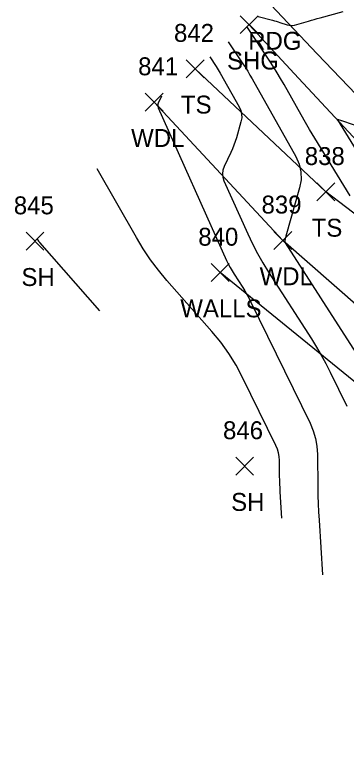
# Model space of a CAD drawing. Extents: x 1592612 to 1596497, y 111838 to 113741.
# Drawn here: x 1592636.6 to 1592673.5, y 113548.4 to 113631.2 of the extents above; entities that cross this region are included whole.
import ezdxf

# ---------------------------------------------------------------- set-up
doc = ezdxf.new("R2010")
doc.units = 0
for name, color, linetype in [('L_A', 7, 'Continuous'), ('L_I', 7, 'Continuous'), ('L_TIC', 7, 'Continuous'), ('LAWA', 7, 'Continuous'), ('LELB', 7, 'Continuous'), ('LSOGCMA', 7, 'Continuous'), ('LSOGCMI', 7, 'Continuous'), ('LWS', 7, 'Continuous'), ('P_A', 7, 'Continuous'), ('P_TIC', 7, 'Continuous'), ('PEU', 7, 'Continuous'), ('PSU', 7, 'Continuous')]:
    doc.layers.add(name, color=color, linetype=linetype)

msp = doc.modelspace()

# ---------------------------------------------------------------- linework, layer by layer
at = {"layer": 'L_TIC'}
for points in [[(1592655.68, 113624.229), (1592657.68, 113626.229)], [(1592657.68, 113624.229), (1592655.68, 113626.229)], [(1592651.114, 113620.499), (1592653.114, 113622.499)], [(1592653.114, 113620.499), (1592651.114, 113622.499)], [(1592670.27, 113610.482), (1592672.27, 113612.482)], [(1592672.27, 113610.482), (1592670.27, 113612.482)], [(1592637.809, 113604.981), (1592639.809, 113606.981)], [(1592639.809, 113604.981), (1592637.809, 113606.981)], [(1592665.454, 113605.066), (1592667.454, 113607.066)], [(1592667.454, 113605.066), (1592665.454, 113607.066)], [(1592658.477, 113601.479), (1592660.477, 113603.479)], [(1592660.477, 113601.479), (1592658.477, 113603.479)], [(1592661.205, 113579.88), (1592663.205, 113581.88)], [(1592663.205, 113579.88), (1592661.205, 113581.88)]]:
    msp.add_lwpolyline(points, dxfattribs=at)
at = {"layer": 'LAWA'}
msp.add_lwpolyline([(1592820.49, 113445.204), (1592799.578, 113454.201), (1592791.672, 113482.437), (1592778.021, 113504.51), (1592763.403, 113519.793), (1592739.369, 113545.558), (1592709.175, 113565.248), (1592691.74, 113580.372), (1592683.654, 113590.995), (1592666.454, 113606.066), (1592652.114, 113621.499)], dxfattribs=at)
at = {"layer": 'LELB'}
msp.add_lwpolyline([(1592727.219, 113556.873), (1592716.113, 113565.54), (1592709.175, 113565.248), (1592700.479, 113577.276), (1592699.083, 113585.764), (1592690.53, 113596.781), (1592671.27, 113611.482), (1592656.68, 113625.229)], dxfattribs=at)
at = {"layer": 'LSOGCMA'}
for points in [[(1592663.705, 113631.065), (1592665.32, 113630.643), (1592665.526, 113630.587), (1592665.73, 113630.528), (1592665.934, 113630.465), (1592666.137, 113630.399), (1592666.946, 113630.128), (1592667.149, 113630.076), (1592667.352, 113630.055), (1592667.556, 113630.067), (1592667.76, 113630.11), (1592669.315, 113630.557), (1592669.642, 113630.65), (1592669.97, 113630.743), (1592670.298, 113630.834), (1592670.627, 113630.925), (1592673.206, 113631.629)], [(1592673.987, 113611.032), (1592670.021, 113617.466), (1592669.718, 113617.964), (1592669.42, 113618.464), (1592669.127, 113618.968), (1592668.839, 113619.474), (1592666.601, 113623.458), (1592666.217, 113624.126), (1592665.821, 113624.786), (1592665.413, 113625.438), (1592664.992, 113626.083), (1592662.429, 113629.928)], [(1592646.038, 113598.225), (1592639.344, 113605.822), (1592639.309, 113605.863), (1592639.277, 113605.905), (1592639.248, 113605.95), (1592639.22, 113605.995), (1592639.061, 113606.275)]]:
    msp.add_lwpolyline(points, dxfattribs=at)
at = {"layer": 'LSOGCMI'}
for points in [[(1592660.367, 113628.242), (1592662.01, 113625.777), (1592662.28, 113625.363), (1592662.542, 113624.945), (1592662.796, 113624.522), (1592663.042, 113624.093), (1592667.906, 113615.436), (1592668.283, 113614.592), (1592668.478, 113613.726), (1592668.491, 113612.838), (1592668.322, 113611.929), (1592666.794, 113606.534), (1592666.777, 113606.471), (1592666.76, 113606.408), (1592666.745, 113606.344), (1592666.73, 113606.281), (1592666.674, 113606.025), (1592666.667, 113605.963), (1592666.671, 113605.902), (1592666.688, 113605.844), (1592666.717, 113605.788), (1592678.528, 113587.389)], [(1592658.305, 113626.557), (1592659.029, 113625.47), (1592659.148, 113625.288), (1592659.263, 113625.104), (1592659.375, 113624.917), (1592659.483, 113624.729), (1592661.592, 113620.974), (1592661.772, 113620.572), (1592661.865, 113620.159), (1592661.871, 113619.736), (1592661.791, 113619.302), (1592661.284, 113617.513), (1592661.156, 113617.095), (1592661.011, 113616.684), (1592660.848, 113616.279), (1592660.668, 113615.881), (1592659.913, 113614.302), (1592659.77, 113613.906), (1592659.719, 113613.51), (1592659.76, 113613.112), (1592659.893, 113612.713), (1592662.537, 113606.803), (1592663.057, 113605.695), (1592663.618, 113604.61), (1592664.22, 113603.547), (1592664.863, 113602.506), (1592669.652, 113595.067), (1592670.213, 113594.167), (1592670.747, 113593.251), (1592671.253, 113592.321), (1592671.733, 113591.375), (1592673.598, 113587.56)], [(1592652.94, 113622.174), (1592652.57, 113621.4), (1592652.523, 113621.27), (1592652.506, 113621.141), (1592652.52, 113621.011), (1592652.563, 113620.88), (1592660.187, 113603.837), (1592660.375, 113603.437), (1592660.577, 113603.045), (1592660.795, 113602.661), (1592661.027, 113602.285), (1592661.985, 113600.797), (1592662.219, 113600.422), (1592662.441, 113600.04), (1592662.652, 113599.652), (1592662.852, 113599.258), (1592669.497, 113585.664), (1592669.851, 113584.829), (1592670.106, 113583.97), (1592670.264, 113583.087), (1592670.323, 113582.182), (1592670.365, 113578.513), (1592670.382, 113577.596), (1592670.41, 113576.679), (1592670.451, 113575.763), (1592670.504, 113574.848), (1592670.897, 113568.737)], [(1592675.629, 113618.513), (1592673.031, 113619.401), (1592672.999, 113619.412), (1592672.967, 113619.423), (1592672.935, 113619.434), (1592672.903, 113619.446), (1592672.761, 113619.499), (1592672.736, 113619.508), (1592672.712, 113619.516), (1592672.687, 113619.524), (1592672.662, 113619.532), (1592672.563, 113619.562), (1592672.543, 113619.566), (1592672.533, 113619.563), (1592672.532, 113619.552), (1592672.541, 113619.533), (1592678.211, 113610.334)], [(1592666.36, 113575.076), (1592666.172, 113577.997), (1592666.146, 113578.434), (1592666.127, 113578.872), (1592666.113, 113579.31), (1592666.105, 113579.749), (1592666.086, 113581.502), (1592666.057, 113581.935), (1592665.982, 113582.357), (1592665.86, 113582.768), (1592665.69, 113583.167), (1592661.97, 113590.779), (1592661.242, 113592.15), (1592660.428, 113593.463), (1592659.528, 113594.719), (1592658.541, 113595.917), (1592653.529, 113601.604), (1592652.585, 113602.732), (1592651.702, 113603.905), (1592650.881, 113605.12), (1592650.12, 113606.38), (1592645.744, 113614.07)]]:
    msp.add_lwpolyline(points, dxfattribs=at)
at = {"layer": 'LWS'}
msp.add_lwpolyline([(1592776.94, 113499.802), (1592759.191, 113514.391), (1592732.196, 113536.522), (1592707.136, 113559.182), (1592694.649, 113568.778), (1592678.365, 113587.138), (1592659.477, 113602.479)], dxfattribs=at)
at = {"layer": 'P_TIC'}
for points in [[(1592661.695, 113629.145), (1592663.695, 113631.145)], [(1592663.695, 113629.145), (1592661.695, 113631.145)]]:
    msp.add_lwpolyline(points, dxfattribs=at)
at = {"layer": 'PEU'}
msp.add_lwpolyline([(1592744.662, 113547.12), (1592739.305, 113552.768), (1592733.948, 113558.416), (1592728.591, 113564.063), (1592723.227, 113570.045), (1592717.863, 113576.027), (1592712.498, 113582.009), (1592707.134, 113587.991), (1592701.82, 113593.634), (1592696.506, 113599.278), (1592691.192, 113604.921), (1592685.878, 113610.564), (1592680.686, 113616.008), (1592675.493, 113621.453), (1592670.301, 113626.898), (1592665.108, 113632.343)], dxfattribs=at)
at = {"layer": 'PSU'}
msp.add_lwpolyline([(1592662.695, 113630.145), (1592667.742, 113624.713), (1592672.79, 113619.28), (1592677.837, 113613.848), (1592682.884, 113608.415), (1592688.208, 113602.611), (1592693.531, 113596.808), (1592698.855, 113591.004), (1592704.178, 113585.201), (1592709.634, 113579.332), (1592715.09, 113573.464), (1592720.547, 113567.595), (1592726.003, 113561.726), (1592731.459, 113556.245), (1592736.914, 113550.763), (1592742.37, 113545.281)], dxfattribs=at)

# ---------------------------------------------------------------- texts
at = {"layer": 'L_A'}
for s, p in [('TS', (1592655.09, 113620.229)), ('WDL', (1592649.531, 113616.499)), ('TS', (1592669.679, 113606.482)), ('SH', (1592637.297, 113600.981)), ('WDL', (1592663.872, 113601.066)), ('WALLS', (1592655.02, 113597.479)), ('SH', (1592660.693, 113575.88))]:
    msp.add_text(s, height=2, dxfattribs=at).set_placement(p)
at = {"layer": 'L_I'}
for s, p in [('842', (1592654.318, 113628.229)), ('841', (1592650.318, 113624.499)), ('838', (1592668.908, 113614.482)), ('845', (1592636.447, 113608.981)), ('839', (1592664.084, 113609.066)), ('840', (1592657.028, 113605.479)), ('846', (1592659.788, 113583.88))]:
    msp.add_text(s, height=2, dxfattribs=at).set_placement(p)
at = {"layer": 'P_A'}
for s, p in [('RDG', (1592662.597, 113627.343)), ('SHG', (1592660.23, 113625.145))]:
    msp.add_text(s, height=2, dxfattribs=at).set_placement(p)

doc.saveas('drawing.dxf')
